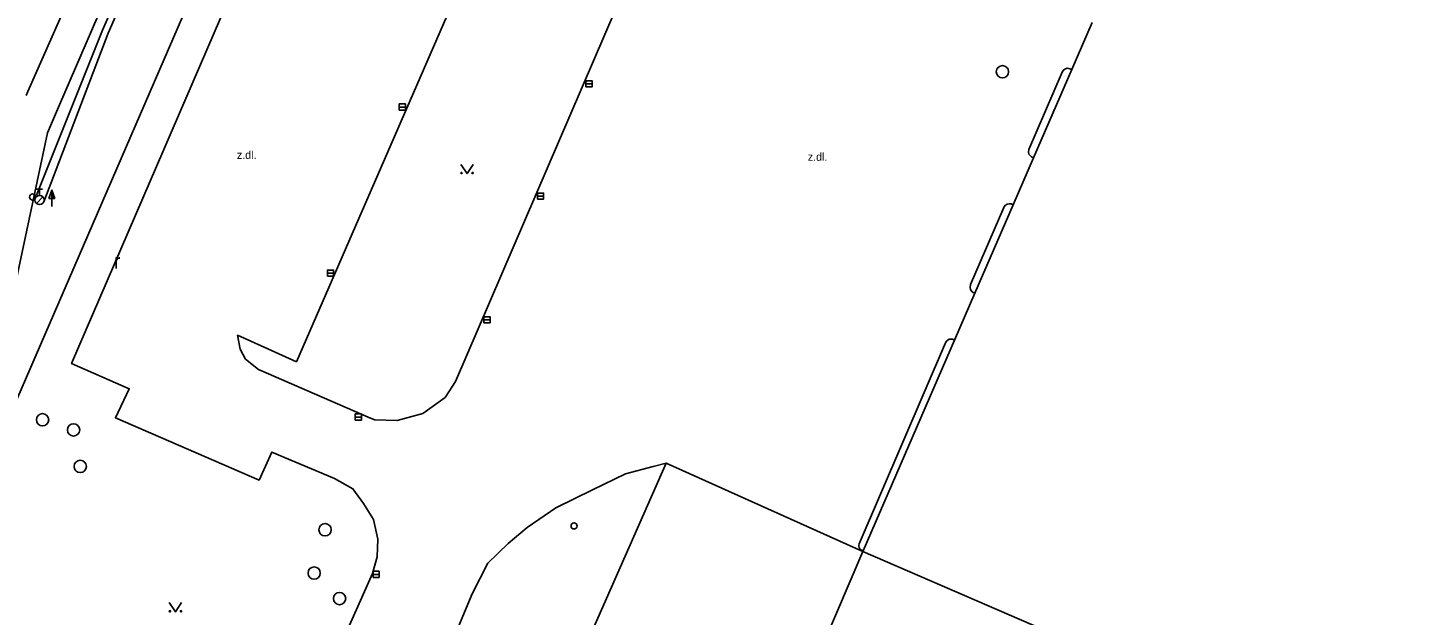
# Model space of a CAD drawing. Extents: x -596024 to -594475, y -1163820 to -1161957.
# Drawn here: x -594794.1 to -594681.4, y -1162541.3 to -1162493.5 of the extents above; entities that cross this region are included whole.
import ezdxf

# ---------------------------------------------------------------- set-up
doc = ezdxf.new("R2010")
doc.units = 0
for name, color, linetype in [('Level 10', 7, 'Continuous'), ('Level 11', 7, 'Continuous'), ('Level 14', 7, 'Continuous'), ('Level 25', 7, 'Continuous'), ('Level 27', 7, 'Continuous'), ('Level 28', 7, 'Continuous'), ('Level 36', 7, 'Continuous'), ('Level 40', 7, 'Continuous'), ('Level 5', 7, 'Continuous'), ('Level 7', 7, 'Continuous')]:
    doc.layers.add(name, color=color, linetype=linetype)

msp = doc.modelspace()

# ---------------------------------------------------------------- linework, layer by layer
at = {"layer": 'Level 10'}
msp.add_lwpolyline([(-594789.14, -1162487.39), (-594794.12, -1162498.7), (-594794.26, -1162499.01)], dxfattribs=at)
at = {"layer": 'Level 11'}
for points in [[(-594768.86, -1162544.01), (-594766.1, -1162537.86), (-594765.74, -1162536.52), (-594765.67, -1162535.07), (-594766.03, -1162533.47), (-594766.83, -1162532.17), (-594767.7, -1162530.98), (-594769.19, -1162530.14), (-594774.28, -1162528), (-594775.32, -1162530.27), (-594787, -1162525.21), (-594785.87, -1162522.85), (-594790.56, -1162520.79), (-594769.77, -1162472.54), (-594764.91, -1162474.63)], [(-594749.25, -1162479.04), (-594747.82, -1162481.46), (-594746.79, -1162482.9), (-594746.14, -1162484.93), (-594745.78, -1162487.03), (-594745.78, -1162489.06), (-594745.92, -1162490.88), (-594746.31, -1162491.92), (-594759.37, -1162522.25), (-594760.2, -1162523.56), (-594762.01, -1162524.86), (-594764.11, -1162525.44), (-594765.93, -1162525.37), (-594766.27, -1162525.25), (-594775.36, -1162521.29), (-594776.44, -1162520.44)], [(-594772.28, -1162520.67), (-594754.29, -1162479.2)], [(-594786.68, -1162488.53), (-594791.54, -1162499.78), (-594792.52, -1162502.05), (-594795.23, -1162514.8)], [(-594709.29, -1162496.91), (-594709.53, -1162496.82), (-594709.67, -1162496.8), (-594709.87, -1162496.88), (-594709.98, -1162496.95), (-594710.07, -1162497.12), (-594712.78, -1162503.39), (-594712.82, -1162503.61), (-594712.78, -1162503.79), (-594712.65, -1162503.93), (-594712.58, -1162504.01), (-594712.41, -1162504.09)], [(-594714.06, -1162507.9), (-594714.23, -1162507.82), (-594714.39, -1162507.83), (-594714.55, -1162507.86), (-594714.68, -1162507.92), (-594714.81, -1162508.08), (-594714.83, -1162508.12), (-594717.53, -1162514.39), (-594717.56, -1162514.63), (-594717.54, -1162514.79), (-594717.42, -1162514.94), (-594717.31, -1162515.02), (-594717.17, -1162515.08)], [(-594776.44, -1162520.44), (-594776.86, -1162519.64), (-594777.07, -1162518.5), (-594774.61, -1162519.6), (-594772.28, -1162520.67)], [(-594718.82, -1162518.91), (-594719, -1162518.83), (-594719.13, -1162518.81), (-594719.26, -1162518.82), (-594719.37, -1162518.89), (-594719.48, -1162518.99), (-594719.56, -1162519.13), (-594726.57, -1162535.47), (-594726.6, -1162535.56), (-594726.6, -1162535.65), (-594726.57, -1162535.75), (-594726.51, -1162535.87), (-594726.43, -1162535.94), (-594726.35, -1162535.97), (-594726.24, -1162536.02)], [(-594761.3, -1162547.37), (-594758.02, -1162539.52), (-594756.75, -1162537.02), (-594755.08, -1162535.43), (-594753.55, -1162534.12), (-594751.23, -1162532.52), (-594748.25, -1162531.07), (-594745.56, -1162529.76), (-594743.31, -1162529.18), (-594742.24, -1162528.9)], [(-594726.27, -1162536.09), (-594732.77, -1162551.3), (-594749.03, -1162544.26), (-594742.24, -1162528.9)], [(-594742.24, -1162528.9), (-594726.27, -1162536.09)]]:
    msp.add_lwpolyline(points, dxfattribs=at)
at = {"layer": 'Level 14'}
for points in [[(-594788.05, -1162493.71), (-594786.22, -1162489.57), (-594782.68, -1162481.57)], [(-594782.38, -1162481.97), (-594785.76, -1162489.77), (-594787.58, -1162493.96)], [(-594793.42, -1162507.11), (-594788.05, -1162493.71)], [(-594787.58, -1162493.96), (-594792.8, -1162507.66)]]:
    msp.add_lwpolyline(points, dxfattribs=at)
at = {"layer": 'Level 25'}
for p, q in [((-594792.41, -1162507.38), (-594792.16, -1162506.7)), ((-594792.16, -1162507.38), (-594792.41, -1162507.38)), ((-594792.16, -1162508.03), (-594792.16, -1162507.38))]:
    msp.add_line(p, q, dxfattribs=at)
for points in [[(-594791.91, -1162507.38), (-594792.16, -1162507.38), (-594792.16, -1162506.7), (-594792.16, -1162506.7)], [(-594791.97, -1162507.34), (-594792.12, -1162507.34), (-594792.12, -1162506.93)], [(-594792.02, -1162507.3), (-594792.08, -1162507.3), (-594792.08, -1162507.15)]]:
    msp.add_lwpolyline(points, close=True, dxfattribs=at)
at = {"layer": 'Level 27'}
for p, q in [((-594748.77, -1162498.06), (-594748.27, -1162498.06)), ((-594763.94, -1162499.95), (-594763.44, -1162499.95)), ((-594752.71, -1162507.19), (-594752.21, -1162507.19)), ((-594769.77, -1162513.45), (-594769.27, -1162513.45)), ((-594757.06, -1162517.25), (-594756.56, -1162517.25)), ((-594767.51, -1162525.15), (-594767.01, -1162525.15)), ((-594766.07, -1162537.94), (-594765.57, -1162537.94))]:
    msp.add_line(p, q, dxfattribs=at)
for points in [[(-594748.77, -1162498.31), (-594748.27, -1162498.31), (-594748.27, -1162497.81), (-594748.77, -1162497.81)], [(-594763.94, -1162500.2), (-594763.44, -1162500.2), (-594763.44, -1162499.7), (-594763.94, -1162499.7)], [(-594752.71, -1162507.44), (-594752.21, -1162507.44), (-594752.21, -1162506.94), (-594752.71, -1162506.94)], [(-594769.77, -1162513.7), (-594769.27, -1162513.7), (-594769.27, -1162513.2), (-594769.77, -1162513.2)], [(-594757.06, -1162517.5), (-594756.56, -1162517.5), (-594756.56, -1162517), (-594757.06, -1162517)], [(-594767.51, -1162525.4), (-594767.01, -1162525.4), (-594767.01, -1162524.9), (-594767.51, -1162524.9)], [(-594766.07, -1162538.19), (-594765.57, -1162538.19), (-594765.57, -1162537.69), (-594766.07, -1162537.69)]]:
    msp.add_lwpolyline(points, close=True, dxfattribs=at)
for centre in [(-594714.93, -1162497.08), (-594792.92, -1162525.37), (-594790.4, -1162526.2), (-594789.85, -1162529.16), (-594769.97, -1162534.31), (-594770.85, -1162537.83), (-594768.79, -1162539.91)]:
    msp.add_circle(centre, 0.5, dxfattribs=at)
at = {"layer": 'Level 28'}
for p, q in [((-594793.41, -1162506.64), (-594792.91, -1162506.64)), ((-594793.16, -1162507.14), (-594793.16, -1162506.64)), ((-594793.42, -1162507.78), (-594792.89, -1162507.25))]:
    msp.add_line(p, q, dxfattribs=at)
for centre, radius in [((-594793.73, -1162507.27), 0.25), ((-594793.16, -1162507.51), 0.375), ((-594749.73, -1162534), 0.25)]:
    msp.add_circle(centre, radius, dxfattribs=at)
at = {"layer": 'Level 36'}
for points in [[(-594758.93, -1162504.61), (-594758.43, -1162505.36), (-594757.93, -1162504.61)], [(-594782.62, -1162540.24), (-594782.12, -1162540.99), (-594781.62, -1162540.24)]]:
    msp.add_lwpolyline(points, dxfattribs=at)
for centre in [(-594758.88, -1162505.31), (-594757.98, -1162505.31), (-594782.57, -1162540.94), (-594781.67, -1162540.94)]:
    msp.add_circle(centre, 0.05, dxfattribs=at)
at = {"layer": 'Level 5'}
for points in [[(-594709.29, -1162496.91), (-594707.64, -1162493.09)], [(-594712.41, -1162504.09), (-594709.29, -1162496.91)], [(-594714.06, -1162507.9), (-594712.41, -1162504.09)], [(-594717.17, -1162515.08), (-594714.06, -1162507.9)], [(-594718.82, -1162518.91), (-594717.17, -1162515.08)], [(-594726.24, -1162536.02), (-594718.82, -1162518.91)], [(-594726.27, -1162536.09), (-594726.24, -1162536.02)], [(-594659.39, -1162565.05), (-594726.27, -1162536.09)]]:
    msp.add_lwpolyline(points, dxfattribs=at)
at = {"layer": 'Level 7'}
msp.add_lwpolyline([(-594769.03, -1162543.94), (-594781.09, -1162555.04), (-594799.88, -1162546.92), (-594802.36, -1162540.69), (-594768.78, -1162463.11)], dxfattribs=at)

# ---------------------------------------------------------------- texts
at = {"layer": 'Level 36'}
msp.add_text('r', height=1.2, dxfattribs=at).set_placement((-594787.12, -1162513.09))
at = {"layer": 'Level 40'}
for p in [(-594777.13, -1162504.17), (-594730.75, -1162504.32)]:
    msp.add_text('z.dl.', height=0.65, dxfattribs=at).set_placement(p)

doc.saveas('drawing.dxf')
